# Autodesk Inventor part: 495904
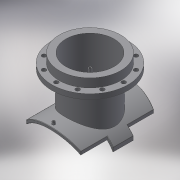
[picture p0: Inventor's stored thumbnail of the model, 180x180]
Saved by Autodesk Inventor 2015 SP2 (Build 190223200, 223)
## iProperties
Created: 2017-10
Part Number: 495904
Material: Generic
Description: PLASSON FLANGED BRANCH SADDLE 250-400X80
Document SubType Name: Modeling
Designer: KIM
Density: 1 g/cm^3
Appearance: Default
Author: KIM
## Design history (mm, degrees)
derived "495904.ipt"
feature "Solid1::495904.ipt"
feature "Solid2::495904.ipt"
tag "TaggingFeature1"
body "Solid1"
other parameters: "d1" = 15, "d2" = 274.5, "d4" = 0, "d5" = 305, "d6" = 75, "d7" = 0, "d11" = 2, "d12" = 225.6, "d13" = 14, "d14" = 135, "d16" = 5 deg, "d18" = 4, "d19" = 14, "d20" = 0, "d21" = 3, "d22" = 0, "d23" = 317, "d36" = 135, "d38" = 0, "d39" = 2, "d40" = 102, "d42" = 138, "d44" = 81.6, "d46" = 110.4, "d47" = 16, "d48" = 10.4, "d49" = 71.4, "d51" = 408, "d53" = 0, "d54" = 18, "d57" = 0, "d59" = 360 deg, "d63" = 0, "d_1" = 138, "B_" = 305, "H_" = 102, "x_" = 15, "D_" = 16, "s_" = 18
